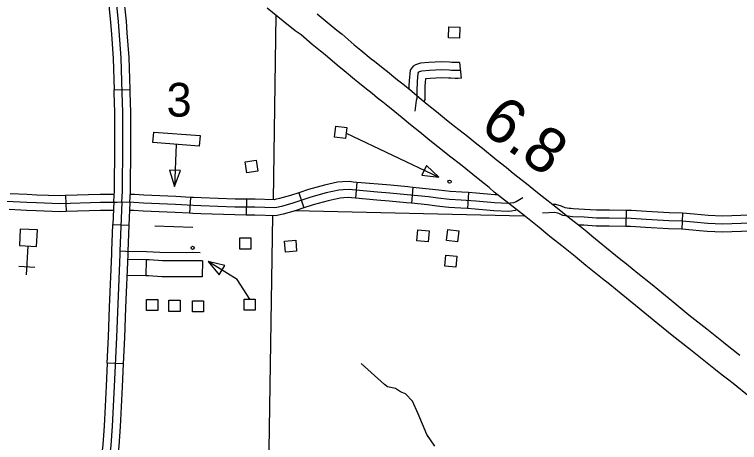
# Model space of a CAD drawing. Extents: x 61396 to 64680, y 55472 to 57605.
# Drawn here: x 62213.6 to 62426.4, y 56474.2 to 56599.7 of the extents above; entities that cross this region are included whole.
import ezdxf

# ---------------------------------------------------------------- set-up
doc = ezdxf.new("R2010")
doc.units = 0
for name, color, linetype in [('15', 7, 'Continuous'), ('31', 7, 'Continuous'), ('32', 7, 'Continuous'), ('35', 7, 'Continuous'), ('45', 7, 'Continuous'), ('48', 7, 'Continuous'), ('5', 7, 'Continuous'), ('56', 7, 'Continuous'), ('57', 7, 'Continuous')]:
    doc.layers.add(name, color=color, linetype=linetype)

msp = doc.modelspace()

# ---------------------------------------------------------------- linework, layer by layer
at = {"layer": '15'}
for p, q in [((62424.3, 56501.56), (62424.22, 56501.62)), ((62419.46, 56495.43), (62419.39, 56495.48))]:
    msp.add_line(p, q, dxfattribs=at)
for points in [[(62419.39, 56495.48), (62416.93, 56497.46), (62415.48, 56498.6), (62412.02, 56501.36), (62406.71, 56505.56), (62402.46, 56509.02), (62395.93, 56514.39), (62391.66, 56517.77), (62388.33, 56520.5), (62386.25, 56522.16), (62381.33, 56526.11), (62378.17, 56528.77), (62376.7, 56529.94), (62374.3, 56531.86), (62371.22, 56534.25), (62369.58, 56535.62), (62367.6, 56537.21), (62363.67, 56540.37), (62361.86, 56541.79), (62359.58, 56543.59), (62355.7, 56546.66), (62354.43, 56547.65), (62352.96, 56548.94), (62350.18, 56551.1), (62346.07, 56554.43), (62344.5, 56555.68), (62341.75, 56557.85), (62337.89, 56560.87), (62335.54, 56562.74), (62332.6, 56565.19), (62329.83, 56567.4), (62327.43, 56569.37), (62325.25, 56571.2), (62322.75, 56573.26), (62321.72, 56574.03), (62320.17, 56575.23), (62318.63, 56576.53), (62316.49, 56578.24), (62314.43, 56579.88), (62313.42, 56580.67), (62310.36, 56583.18), (62308.32, 56584.86), (62304.79, 56587.92), (62303.4, 56589.01), (62301.02, 56590.94), (62297.74, 56593.72), (62296.02, 56594.91), (62292.45, 56597.78), (62287.76, 56601.55)], [(62302.51, 56599.92), (62306, 56596.96), (62308.28, 56595.11), (62309.77, 56593.94), (62313.36, 56590.83), (62315.32, 56589.22), (62318.31, 56586.76), (62319.28, 56586), (62321.35, 56584.35), (62323.58, 56582.58), (62325.08, 56581.31), (62326.46, 56580.24), (62327.59, 56579.4), (62330.24, 56577.21), (62332.42, 56575.39), (62334.75, 56573.47), (62337.54, 56571.25), (62340.47, 56568.8), (62342.73, 56567.01), (62346.59, 56563.99), (62349.35, 56561.8), (62350.95, 56560.53), (62355.04, 56557.22), (62357.94, 56554.96), (62359.4, 56553.68), (62360.52, 56552.81), (62364.42, 56549.72), (62366.69, 56547.93), (62368.53, 56546.48), (62372.5, 56543.3), (62374.53, 56541.66), (62376.12, 56540.34), (62379.14, 56538), (62381.59, 56536.03), (62383.12, 56534.81), (62386.29, 56532.14), (62391.13, 56528.25), (62393.24, 56526.57), (62396.56, 56523.85), (62400.84, 56520.47), (62407.41, 56515.07), (62411.6, 56511.65), (62416.88, 56507.47), (62420.31, 56504.73), (62421.78, 56503.59), (62424.3, 56501.56)], [(62424.22, 56501.62), (62426.57, 56499.81)], [(62429.37, 56487.57), (62424.58, 56491.44), (62423.28, 56492.47), (62421.78, 56493.64), (62419.46, 56495.43)]]:
    msp.add_lwpolyline(points, dxfattribs=at)
at = {"layer": '31'}
for p, q in [((62242.91, 56577.62), (62247.59, 56577.76)), ((62247.59, 56577.76), (62247.59, 56577.76)), ((62242.54, 56538.15), (62247.22, 56537.88)), ((62245.52, 56497.2), (62240.84, 56497.41))]:
    msp.add_line(p, q, dxfattribs=at)
for points in [[(62245.16, 56544.7), (62245.34, 56547.91), (62245.4, 56561.59), (62245.46, 56571.07), (62245.28, 56576.79), (62244.97, 56587), (62244.12, 56597.58), (62243.33, 56605.66), (62242.91, 56611.25), (62241.75, 56626.15), (62241.5, 56630.57), (62241.19, 56634.67)], [(62240.62, 56610.42), (62241, 56605.46), (62241.79, 56597.37), (62242.06, 56593.98)], [(62246.73, 56594.35), (62246.46, 56597.78), (62245.67, 56605.86), (62245.29, 56610.78)], [(62242.06, 56593.98), (62242.63, 56586.87), (62242.91, 56577.62)], [(62247.59, 56577.76), (62247.31, 56587.13), (62246.73, 56594.35)], [(62243.05, 56561.2), (62243.06, 56561.6), (62243.12, 56571.04), (62242.93, 56576.71), (62242.91, 56577.62)], [(62247.74, 56561.18), (62247.74, 56561.58), (62247.8, 56571.1), (62247.62, 56576.86), (62247.59, 56577.76)], [(62242.82, 56544.83), (62242.99, 56547.98), (62243.05, 56561.2)], [(62247.5, 56544.57), (62247.68, 56547.84), (62247.74, 56561.18)], [(62242.82, 56544.83), (62242.54, 56538.15)], [(62245.16, 56544.7), (62244.56, 56530.28)], [(62247.5, 56544.57), (62247.22, 56537.88)], [(62242.22, 56530.37), (62242.54, 56538.15)], [(62247.22, 56537.88), (62246.9, 56530.18)], [(62244.56, 56530.28), (62244.52, 56529.42), (62243.54, 56505.11), (62242.87, 56490.59), (62242.26, 56478.95), (62241.89, 56473.26), (62240.91, 56465.17), (62238.46, 56449.12), (62236.44, 56436.69), (62233.62, 56421.41), (62232.7, 56416.45), (62230.99, 56405.54), (62229.82, 56398.84), (62228.69, 56392.56), (62228.26, 56390.45), (62227.71, 56388.65)], [(62241.55, 56513.88), (62242.18, 56529.52), (62242.22, 56530.37)], [(62246.9, 56530.18), (62246.87, 56529.33), (62246.24, 56513.7)], [(62240.84, 56497.41), (62241.2, 56505.21), (62241.55, 56513.88)], [(62246.24, 56513.7), (62245.89, 56505), (62245.52, 56497.2)], [(62240.84, 56497.41), (62240.53, 56490.71), (62240.02, 56480.95)], [(62245.52, 56497.2), (62245.21, 56490.47), (62244.7, 56480.7)], [(62240.02, 56480.95), (62239.92, 56479.09), (62239.56, 56473.47), (62238.59, 56465.49), (62238.48, 56464.76)], [(62244.7, 56480.7), (62244.6, 56478.81), (62244.23, 56473.04), (62243.23, 56464.85), (62243.11, 56464.05)]]:
    msp.add_lwpolyline(points, dxfattribs=at)
at = {"layer": '32'}
for p, q in [((62344.24, 56585.68), (62344.73, 56581.02)), ((62314.14, 56550.49), (62313.71, 56545.82)), ((62297.11, 56547.45), (62298.59, 56543.01)), ((62330.59, 56549), (62330.12, 56544.34)), ((62346.92, 56547.46), (62346.64, 56542.78)), ((62228.59, 56546.6), (62228.75, 56541.92)), ((62265.31, 56546.08), (62265.04, 56541.4)), ((62281.69, 56545.56), (62281.64, 56540.87)), ((62393.2, 56542.24), (62393.09, 56537.56)), ((62409.7, 56541.43), (62409.55, 56536.74)), ((62252.28, 56527.77), (62252.21, 56523.09)), ((62268.77, 56527.46), (62268.7, 56522.77))]:
    msp.add_line(p, q, dxfattribs=at)
for points in [[(62344.24, 56585.68), (62343.62, 56585.62), (62343.12, 56585.62), (62342.02, 56585.69), (62341.29, 56585.73), (62338.99, 56585.84), (62335.28, 56585.67), (62332.76, 56585.43), (62331.88, 56585.19), (62331.36, 56584.96), (62330.65, 56584.56), (62329.79, 56583.36), (62329.44, 56580.25), (62329.39, 56578.76)], [(62344.48, 56583.35), (62343.74, 56583.28), (62343.04, 56583.28), (62341.87, 56583.35), (62341.17, 56583.39), (62338.99, 56583.49), (62335.44, 56583.33), (62333.18, 56583.12), (62332.68, 56582.98), (62332.42, 56582.87), (62332.25, 56582.77), (62332.05, 56582.5), (62331.78, 56580.08), (62331.68, 56577.22), (62331.72, 56576.13), (62331.72, 56575.48), (62331.7, 56575.11), (62331.57, 56574.53), (62331.45, 56573.69), (62331.14, 56571.38)], [(62344.73, 56581.02), (62343.87, 56580.93), (62342.96, 56580.93), (62341.73, 56581.01), (62341.05, 56581.05), (62338.99, 56581.14), (62335.61, 56581), (62334.23, 56580.86), (62334.12, 56579.91), (62334.07, 56578.6)], [(62329.39, 56578.76), (62329.36, 56577.93)], [(62334.07, 56578.6), (62334.03, 56577.22), (62334.07, 56576.17), (62334.07, 56575.42), (62334.03, 56574.78), (62333.89, 56574.18)], [(62314.14, 56550.49), (62313.08, 56550.58), (62312.1, 56550.74), (62309.95, 56550.66), (62308.48, 56550.51), (62304.59, 56549.67), (62299.96, 56548.4), (62297.11, 56547.45)], [(62330.59, 56549), (62329.1, 56549.15), (62323.97, 56549.66), (62320.39, 56549.93), (62314.14, 56550.49)], [(62228.59, 56546.6), (62227.04, 56546.55), (62220.19, 56546.77), (62217.39, 56546.88), (62212.31, 56547.16)], [(62242.94, 56546.94), (62238.82, 56546.96), (62228.59, 56546.6)], [(62362.84, 56545.99), (62360.86, 56544.78), (62360.05, 56544.5), (62359.25, 56544.37), (62358.45, 56544.29), (62354.49, 56544.48), (62349, 56544.99), (62344.77, 56545.24), (62341.32, 56545.42), (62337.85, 56545.82), (62335.11, 56546.19), (62328.87, 56546.82), (62323.77, 56547.32), (62320.2, 56547.59), (62312.79, 56548.26), (62311.95, 56548.39), (62310.12, 56548.32), (62308.85, 56548.19), (62305.15, 56547.39), (62300.64, 56546.15), (62295.3, 56544.39), (62291.97, 56543.42), (62290.66, 56543.15), (62290.06, 56543.02), (62284.19, 56543.19), (62278.35, 56543.25), (62268.37, 56543.62), (62266.1, 56543.69), (62260.87, 56543.99), (62251.52, 56544.42), (62248.65, 56544.55), (62245.16, 56544.7)], [(62297.11, 56547.45), (62294.61, 56546.63), (62291.4, 56545.7), (62290.17, 56545.44), (62289.84, 56545.37), (62284.24, 56545.53), (62281.69, 56545.56)], [(62346.92, 56547.46), (62344.9, 56547.58), (62341.51, 56547.76), (62338.14, 56548.15), (62335.39, 56548.52), (62330.59, 56549)], [(62355.55, 56546.78), (62354.65, 56546.82), (62349.17, 56547.33), (62346.92, 56547.46)], [(62245.16, 56544.7), (62243.79, 56544.59), (62238.85, 56544.62), (62227.04, 56544.2), (62220.1, 56544.43), (62217.28, 56544.54), (62211.29, 56544.87), (62208.35, 56544.87)], [(62248.8, 56546.89), (62248.76, 56546.89), (62247.63, 56546.94)], [(62265.31, 56546.08), (62260.99, 56546.33), (62251.63, 56546.76), (62248.81, 56546.89)], [(62281.69, 56545.56), (62278.41, 56545.6), (62268.45, 56545.96), (62266.21, 56546.03), (62265.31, 56546.08)], [(62313.71, 56545.82), (62312.5, 56545.93), (62311.81, 56546.04), (62310.28, 56545.98), (62309.22, 56545.87), (62305.7, 56545.11), (62301.32, 56543.91), (62298.59, 56543.01)], [(62330.12, 56544.34), (62328.64, 56544.49), (62323.56, 56544.99), (62320, 56545.25), (62313.71, 56545.82)], [(62298.59, 56543.01), (62296, 56542.15), (62292.53, 56541.14), (62291.15, 56540.86), (62290.29, 56540.67), (62284.14, 56540.84), (62281.64, 56540.87)], [(62346.64, 56542.78), (62344.64, 56542.9), (62341.12, 56543.08), (62337.56, 56543.5), (62334.84, 56543.86), (62330.12, 56544.34)], [(62361.11, 56542.38), (62360.62, 56542.21), (62359.54, 56542.05), (62358.51, 56541.95), (62354.32, 56542.15), (62348.82, 56542.65), (62346.64, 56542.78)], [(62376.93, 56542.78), (62376.43, 56542.84), (62375.24, 56543.04), (62374.18, 56543.5), (62372.52, 56544), (62371.68, 56543.95)], [(62393.2, 56542.24), (62388.23, 56542.37), (62384.48, 56542.34), (62380.96, 56542.57), (62377.64, 56542.7), (62376.93, 56542.78)], [(62228.75, 56541.92), (62227.04, 56541.86), (62220.02, 56542.09), (62217.17, 56542.2), (62212.06, 56542.48)], [(62242.71, 56542.25), (62238.89, 56542.27), (62228.75, 56541.92)], [(62248.59, 56542.21), (62248.55, 56542.21), (62247.4, 56542.26)], [(62265.04, 56541.4), (62260.74, 56541.65), (62251.41, 56542.08), (62248.59, 56542.21)], [(62281.64, 56540.87), (62278.29, 56540.91), (62268.3, 56541.28), (62266, 56541.34), (62265.04, 56541.4)], [(62409.62, 56539.08), (62405.72, 56539.21), (62399.02, 56539.55), (62394.59, 56539.87), (62388.21, 56540.02), (62384.41, 56540), (62380.84, 56540.23), (62377.46, 56540.36), (62376.1, 56540.52), (62374.56, 56540.78), (62373.37, 56541.3), (62372.25, 56541.64), (62368.6, 56541.41)], [(62409.7, 56541.43), (62405.81, 56541.56), (62399.16, 56541.89), (62394.71, 56542.21), (62393.2, 56542.24)], [(62393.09, 56537.56), (62388.19, 56537.68), (62384.34, 56537.65), (62380.72, 56537.89), (62379.2, 56537.95)], [(62409.55, 56536.74), (62405.62, 56536.87), (62398.88, 56537.21), (62394.48, 56537.52), (62393.09, 56537.56)], [(62268.11, 56529.84), (62266, 56529.87), (62263.97, 56529.84), (62256.33, 56529.87), (62252.42, 56530.14), (62246.18, 56530.24), (62244.56, 56530.28)], [(62252.28, 56527.77), (62246.81, 56527.86)], [(62268.77, 56527.46), (62266.63, 56527.49), (62264.58, 56527.46), (62257.04, 56527.49), (62253.15, 56527.76), (62252.28, 56527.77)], [(62252.21, 56523.09), (62246.62, 56523.18)], [(62268.7, 56522.77), (62266.63, 56522.81), (62264.61, 56522.77), (62256.87, 56522.81), (62252.95, 56523.07), (62252.21, 56523.09)]]:
    msp.add_lwpolyline(points, dxfattribs=at)
at = {"layer": '35'}
msp.add_lwpolyline([(62336.99, 56473.11), (62334.66, 56476.49), (62332.08, 56482.59), (62330.42, 56486.3), (62328.42, 56488.4), (62326.94, 56489.07), (62325.46, 56489.97), (62323.08, 56490.54), (62322.22, 56491.21), (62315.41, 56497.31)], dxfattribs=at)
at = {"layer": '45'}
for points in [[(62415.15, 56540.94), (62413.09, 56541.14), (62409.7, 56541.43)], [(62431.25, 56540.95), (62429.57, 56540.84), (62421.42, 56540.6), (62417.28, 56540.73), (62415.15, 56540.94)], [(62462.54, 56533.11), (62454.95, 56533.01), (62448.02, 56533.15), (62444.52, 56533.42), (62441.4, 56533.49), (62439.72, 56533.83), (62438.83, 56534.28), (62437.87, 56535.13), (62436.74, 56536.3), (62435.34, 56537.81), (62434.68, 56538.36), (62434.07, 56538.56), (62433.45, 56538.63), (62431.77, 56538.63), (62429.68, 56538.49), (62421.42, 56538.25), (62417.13, 56538.39), (62412.88, 56538.8), (62409.62, 56539.08)], [(62414.7, 56536.27), (62412.66, 56536.47), (62409.55, 56536.74)], [(62431.56, 56536.27), (62429.79, 56536.15), (62421.41, 56535.91), (62416.98, 56536.05), (62414.7, 56536.27)]]:
    msp.add_lwpolyline(points, dxfattribs=at)
at = {"layer": '5'}
for points in [[(62290.31, 56599.49), (62289.55, 56545.38)], [(62286.91, 56378.65), (62289.49, 56540.69)], [(62363.12, 56540.57), (62295.92, 56542.12)]]:
    msp.add_lwpolyline(points, dxfattribs=at)
at = {"layer": '56'}
for points in [[(62341.01, 56592.91), (62341.13, 56596.16), (62344.39, 56596.04), (62344.27, 56592.79)], [(62307.58, 56563.74), (62307.97, 56566.97), (62311.21, 56566.57), (62310.81, 56563.35)], [(62254.25, 56562.13), (62254.48, 56565.25), (62268.11, 56564.23), (62267.88, 56561.12)], [(62281.85, 56553.25), (62281.37, 56556.47), (62284.59, 56556.95), (62285.08, 56553.74)], [(62262.35, 56553.97), (62259.17, 56554.1), (62260.57, 56549.26)], [(62334.58, 56555.46), (62333.21, 56552.59), (62338.21, 56551.96)], [(62331.75, 56533.29), (62332.05, 56536.53), (62335.3, 56536.23), (62335, 56532.99)], [(62340.45, 56533.44), (62340.83, 56536.68), (62344.07, 56536.3), (62343.69, 56533.07)], [(62279.74, 56530.93), (62279.74, 56534.18), (62283, 56534.18), (62283, 56530.93)], [(62293.2, 56529.98), (62292.91, 56533.21), (62296.16, 56533.51), (62296.45, 56530.27)], [(62339.91, 56525.92), (62340.24, 56529.15), (62343.49, 56528.82), (62343.15, 56525.59)], [(62273.69, 56523.36), (62275.38, 56526.07), (62270.48, 56527.24)], [(62252.41, 56512.89), (62252.41, 56516.14), (62255.67, 56516.14), (62255.67, 56512.89)], [(62258.97, 56512.64), (62258.97, 56515.9), (62262.23, 56515.9), (62262.23, 56512.64)], [(62265.83, 56512.49), (62265.83, 56515.74), (62269.09, 56515.74), (62269.09, 56512.49)], [(62281.05, 56512.96), (62281.05, 56516.21), (62284.31, 56516.21), (62284.31, 56512.96)]]:
    msp.add_lwpolyline(points, close=True, dxfattribs=at)
for points in [[(62311.01, 56564.96), (62338.21, 56551.96)], [(62261.06, 56561.62), (62260.57, 56549.26)], [(62254.85, 56537.71), (62265.98, 56537.33)], [(62282.68, 56516.21), (62278.99, 56521.94), (62270.48, 56527.24)]]:
    msp.add_lwpolyline(points, dxfattribs=at)
for centre in [(62341.33, 56550.7), (62265.92, 56531.27)]:
    msp.add_circle(centre, 0.469, dxfattribs=at)
at = {"layer": '57'}
for p, q in [((62217.16, 56523.39), (62217.61, 56531.79)), ((62214.95, 56525.85), (62219.63, 56525.61))]:
    msp.add_line(p, q, dxfattribs=at)
msp.add_lwpolyline([(62215.33, 56536.79), (62215.07, 56531.92), (62220.12, 56531.66), (62220.38, 56536.53)], close=True, dxfattribs=at)

# ---------------------------------------------------------------- texts
at = {"layer": '48'}
msp.add_text('6.8', height=13.2, rotation=324.6929, dxfattribs=at).set_placement((62349.71, 56566.03))
at = {"layer": '56'}
msp.add_text('3', height=9.9, dxfattribs=at).set_placement((62258.26, 56569.77))

doc.saveas('drawing.dxf')
